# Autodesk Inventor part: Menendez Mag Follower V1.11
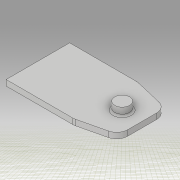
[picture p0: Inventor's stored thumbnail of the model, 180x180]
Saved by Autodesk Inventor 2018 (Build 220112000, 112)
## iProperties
Created: 2019-06
Part Number: Menendez Mag Follower V1.11
Material: Generic
Document SubType Name: Modeling
Designer: Ivan
Density: 1 g/cm^3
Appearance: Default
Author: Ivan
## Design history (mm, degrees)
sketch "Sketch1"
  geometry: L1 (0, 0)-(-19.761, 0); L2 (-30.302, 0)-(-30.302, -15.964); L3 (-19.761, -18.466)-(0, -18.466); L4 (0, -18.466)-(0, 0); L5 (-30.302, -9.233)-(-30.302, -2.502); L6 (-30.302, -2.502)-(-30.302, -15.964); L7 (-30.302, -18.466)-(-19.761, -18.466); L8 (-19.761, -18.466)-(-30.302, -15.964); L9 (-30.302, -2.502)-(-19.761, 0)
  constraints: 18 end point, 2 parallel, 2 point on line, 1 horizontal, 1 perpendicular
  dimensions: "d0" = 30.3022 distance of L3.end L7.start; "d1" = 18.4658 distance of L7.start L2.start; "d2" = 6.731 distance of L5.start L5.end; "d3" = 13.462 distance of L2.end L5.end; "d4" = 10.541 distance of L3.start L7.start
extrude "Extrusion1" new body sketch "Sketch1" distance "d5" = 1.651; taper "d6" = 0 deg
sketch "Sketch2"
  geometry: L1 (0, 0)-(19.761, 0) reference; L2 (30.302, 2.502)-(30.302, 15.964) reference; C1 r 2.159 at (24.587, 9.144)
  constraints: 1 centre point
  dimensions: "d7" = 4.318 diameter of C1; "d8" = 9.144 distance from line of L1 C1.centre; "d9" = 5.715 distance from line of C1.centre L2
extrude "Extrusion2" join sketch "Sketch2" distance "d10" = 2.286; taper "d11" = 0 deg
fillet "Fillet1" dims "d12" = 0.508
fillet "Fillet2" dims "d13" = 3.175
body "Solid1"
